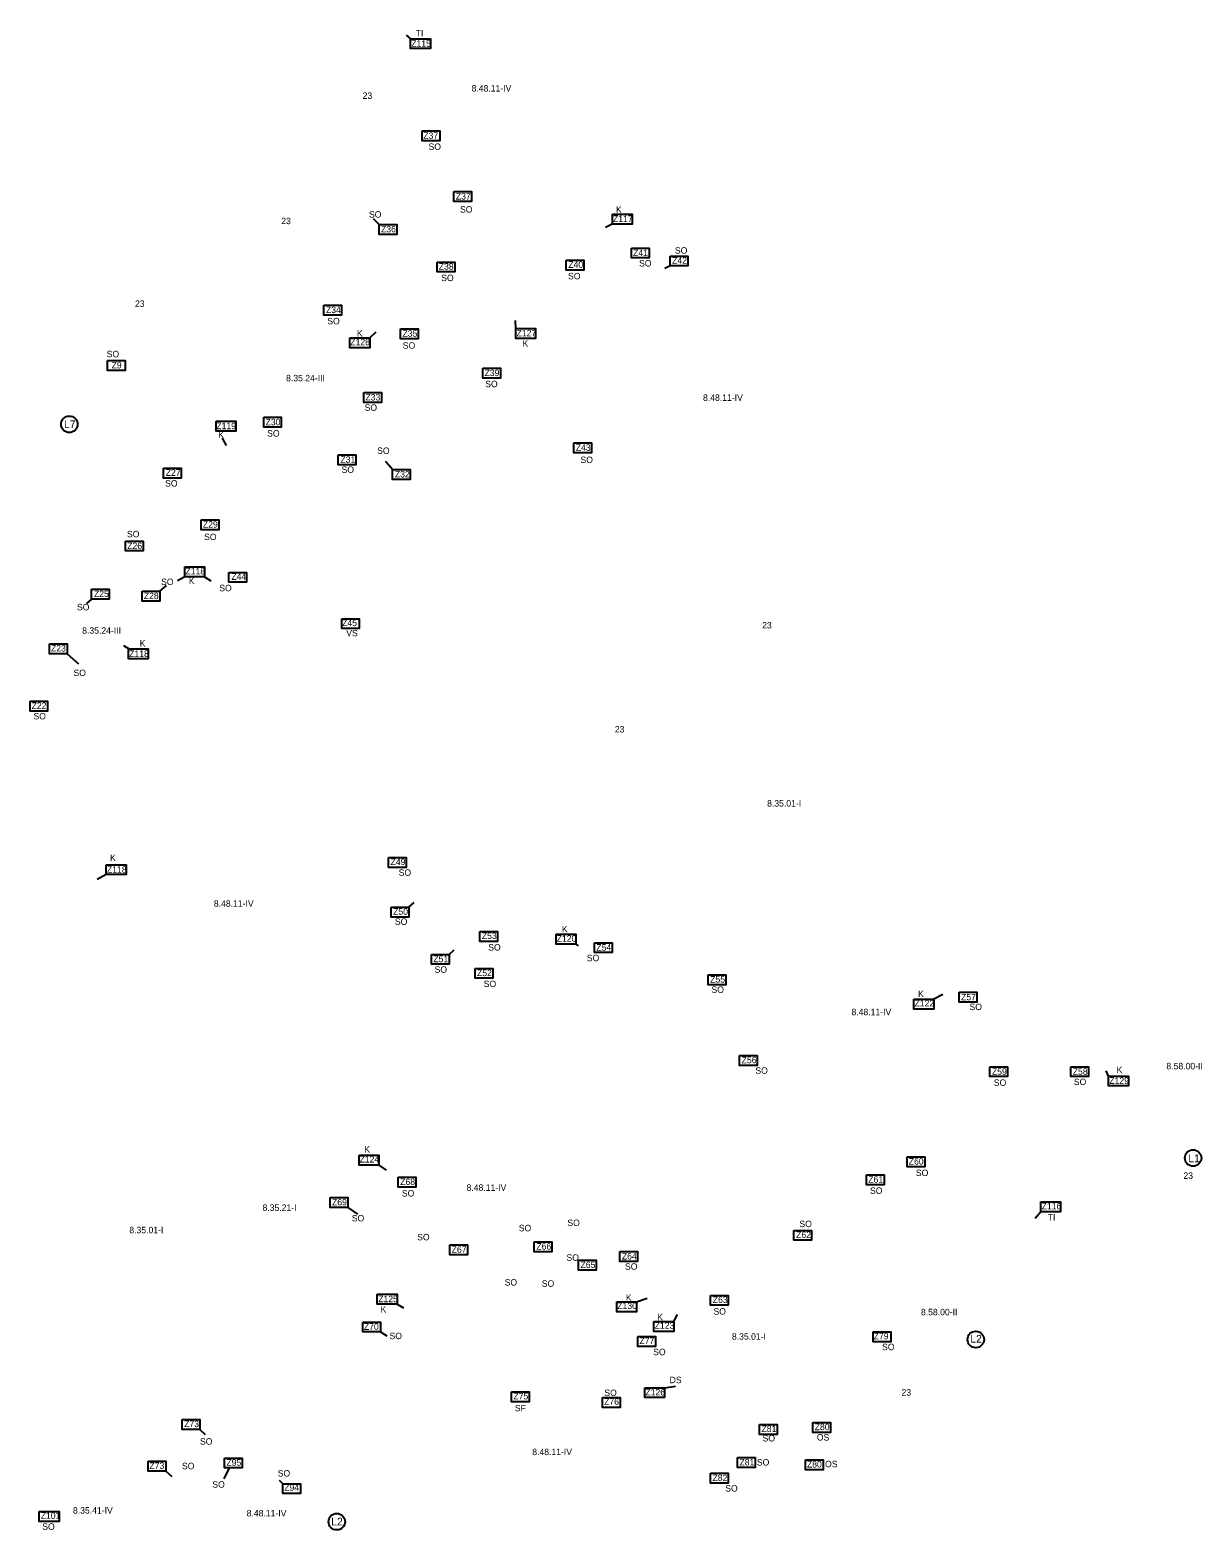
# Model space of a CAD drawing. Extents: x -450307 to -440553, y -1134449 to -1129789.
# Drawn here: x -442371 to -440553, y -1132115 to -1129789 of the extents above; entities that cross this region are included whole.
import ezdxf

# ---------------------------------------------------------------- set-up
doc = ezdxf.new("R2010")
doc.units = 0
for name, color, linetype in [('31_BUDOVY', 7, 'Continuous'), ('Vrstva 18', 7, 'Continuous'), ('Vrstva 28', 7, 'Continuous'), ('Vrstva 36', 7, 'Continuous')]:
    doc.layers.add(name, color=color, linetype=linetype)

msp = doc.modelspace()

# ---------------------------------------------------------------- linework, layer by layer
at = {"layer": '31_BUDOVY'}
msp.add_line((-441524.3, -1131206.4), (-441520.6, -1131209.2), dxfattribs=at)
at = {"layer": 'Vrstva 18'}
for p, q in [((-441780.2, -1129802.1), (-441786.8, -1129796.7)), ((-441829.1, -1130090.3), (-441838, -1130081.7)), ((-441467.9, -1130089.8), (-441478.3, -1130094.9)), ((-441378.1, -1130154.6), (-441386.2, -1130158.4)), ((-441617.6, -1130251.7), (-441617.8, -1130238.9)), ((-441834.5, -1130257.1), (-441844, -1130266.2)), ((-442066.2, -1130432.9), (-442072.4, -1130421.5)), ((-441808.5, -1130470.4), (-441819.7, -1130457.7)), ((-442169.8, -1130659.1), (-442159.4, -1130650.4)), ((-442131, -1130636.5), (-442142.2, -1130643.1)), ((-442100.3, -1130636.5), (-442090.5, -1130642.7)), ((-442275.3, -1130671.3), (-442283.1, -1130678.3)), ((-442217.8, -1130748.4), (-442225.3, -1130743.6)), ((-442313.2, -1130756), (-442295.7, -1130771.4)), ((-442252.6, -1131098.6), (-442266.5, -1131106.3)), ((-441783.2, -1131148.9), (-441775.1, -1131141.9)), ((-441721, -1131222.3), (-441712.8, -1131215.4)), ((-440955.2, -1131284.3), (-440969.1, -1131291.6)), ((-440697.9, -1131411.1), (-440701.8, -1131402.8)), ((-441829.7, -1131549.2), (-441818.5, -1131556.8)), ((-441878.2, -1131614.7), (-441862.9, -1131625)), ((-440803, -1131621.5), (-440811.7, -1131631.9)), ((-441801.4, -1131764.9), (-441791.5, -1131770.7)), ((-441430, -1131761), (-441413.5, -1131755.3)), ((-441372.3, -1131791.6), (-441366.8, -1131780.6)), ((-441827.4, -1131807.9), (-441817.5, -1131813.7)), ((-441386.6, -1131894.3), (-441369.7, -1131891.8)), ((-442107.7, -1131959.2), (-442099, -1131967)), ((-442160.4, -1132023.6), (-442151.1, -1132031.8)), ((-442061.8, -1132018.8), (-442070.5, -1132035.8)), ((-441978.8, -1132043.2), (-441984.2, -1132038.4))]:
    msp.add_line(p, q, dxfattribs=at)
for points in [[(-441780.6, -1129802.1), (-441749.8, -1129802.1), (-441749.8, -1129817.5), (-441780.6, -1129817.5)], [(-441762.9, -1129945.2), (-441735.5, -1129945.2), (-441735.5, -1129960.6), (-441762.9, -1129960.6)], [(-441713.5, -1130039.3), (-441686.2, -1130039.3), (-441686.2, -1130054.7), (-441713.5, -1130054.7)], [(-441467.6, -1130074.4), (-441436.8, -1130074.4), (-441436.8, -1130089.8), (-441467.6, -1130089.8)], [(-441829.1, -1130090.3), (-441801.8, -1130090.3), (-441801.8, -1130105.7), (-441829.1, -1130105.7)], [(-441539.4, -1130145.7), (-441512, -1130145.7), (-441512, -1130161.1), (-441539.4, -1130161.1)], [(-441438.1, -1130126.8), (-441410.7, -1130126.8), (-441410.7, -1130142.2), (-441438.1, -1130142.2)], [(-441378.1, -1130139.2), (-441350.7, -1130139.2), (-441350.7, -1130154.6), (-441378.1, -1130154.6)], [(-441739.6, -1130148.5), (-441712.2, -1130148.5), (-441712.2, -1130163.9), (-441739.6, -1130163.9)], [(-441915.1, -1130215.4), (-441887.7, -1130215.4), (-441887.7, -1130230.8), (-441915.1, -1130230.8)], [(-441796.3, -1130252.1), (-441768.9, -1130252.1), (-441768.9, -1130267.5), (-441796.3, -1130267.5)], [(-441617.6, -1130251.7), (-441586.8, -1130251.7), (-441586.8, -1130267.1), (-441617.6, -1130267.1)], [(-441874.8, -1130266.2), (-441844, -1130266.2), (-441844, -1130281.6), (-441874.8, -1130281.6)], [(-442250.7, -1130301.4), (-442223.3, -1130301.4), (-442223.3, -1130316.8), (-442250.7, -1130316.8)], [(-441668.4, -1130313.2), (-441641, -1130313.2), (-441641, -1130328.6), (-441668.4, -1130328.6)], [(-441853.1, -1130350.9), (-441825.7, -1130350.9), (-441825.7, -1130366.3), (-441853.1, -1130366.3)], [(-442082.4, -1130395.4), (-442051.6, -1130395.4), (-442051.6, -1130410.8), (-442082.4, -1130410.8)], [(-442008.5, -1130389.3), (-441981.2, -1130389.3), (-441981.2, -1130404.7), (-442008.5, -1130404.7)], [(-441893, -1130447.6), (-441865.6, -1130447.6), (-441865.6, -1130463), (-441893, -1130463)], [(-441527.5, -1130428.9), (-441500.2, -1130428.9), (-441500.2, -1130444.3), (-441527.5, -1130444.3)], [(-442163.9, -1130468.1), (-442136.5, -1130468.1), (-442136.5, -1130483.5), (-442163.9, -1130483.5)], [(-441808.5, -1130470.4), (-441781.1, -1130470.4), (-441781.1, -1130485.8), (-441808.5, -1130485.8)], [(-442105.4, -1130548.2), (-442078, -1130548.2), (-442078, -1130563.6), (-442105.4, -1130563.6)], [(-442222.8, -1130581.2), (-442195.5, -1130581.2), (-442195.5, -1130596.5), (-442222.8, -1130596.5)], [(-442130.8, -1130621.2), (-442100.1, -1130621.2), (-442100.1, -1130636.6), (-442130.8, -1130636.6)], [(-442062.5, -1130629.9), (-442035.1, -1130629.9), (-442035.1, -1130645.2), (-442062.5, -1130645.2)], [(-442275.3, -1130655.9), (-442247.9, -1130655.9), (-442247.9, -1130671.3), (-442275.3, -1130671.3)], [(-442197.1, -1130659.1), (-442169.8, -1130659.1), (-442169.8, -1130674.5), (-442197.1, -1130674.5)], [(-441887.5, -1130701.6), (-441860.2, -1130701.6), (-441860.2, -1130716.9), (-441887.5, -1130716.9)], [(-442340.6, -1130740.6), (-442313.2, -1130740.6), (-442313.2, -1130756), (-442340.6, -1130756)], [(-442218.1, -1130748.4), (-442187.4, -1130748.4), (-442187.4, -1130763.8), (-442218.1, -1130763.8)], [(-442370.9, -1130829.7), (-442343.6, -1130829.7), (-442343.6, -1130845.1), (-442370.9, -1130845.1)], [(-441815, -1131072), (-441787.6, -1131072), (-441787.6, -1131087.4), (-441815, -1131087.4)], [(-442252.6, -1131083.2), (-442221.9, -1131083.2), (-442221.9, -1131098.6), (-442252.6, -1131098.6)], [(-441810.6, -1131148.9), (-441783.2, -1131148.9), (-441783.2, -1131164.3), (-441810.6, -1131164.3)], [(-441673.2, -1131186.9), (-441645.8, -1131186.9), (-441645.8, -1131202.2), (-441673.2, -1131202.2)], [(-441555, -1131191), (-441524.3, -1131191), (-441524.3, -1131206.4), (-441555, -1131206.4)], [(-441495.6, -1131204.2), (-441468.2, -1131204.2), (-441468.2, -1131219.6), (-441495.6, -1131219.6)], [(-441748.4, -1131222.3), (-441721, -1131222.3), (-441721, -1131237.7), (-441748.4, -1131237.7)], [(-441680.5, -1131244), (-441653.2, -1131244), (-441653.2, -1131259.4), (-441680.5, -1131259.4)], [(-441319, -1131254), (-441291.6, -1131254), (-441291.6, -1131269.4), (-441319, -1131269.4)], [(-440929.5, -1131281), (-440902.2, -1131281), (-440902.2, -1131296.4), (-440929.5, -1131296.4)], [(-441000, -1131291.8), (-440969.2, -1131291.8), (-440969.2, -1131307.2), (-441000, -1131307.2)], [(-441270.2, -1131379), (-441242.8, -1131379), (-441242.8, -1131394.4), (-441270.2, -1131394.4)], [(-440882, -1131396.5), (-440854.6, -1131396.5), (-440854.6, -1131411.9), (-440882, -1131411.9)], [(-440756.3, -1131396.5), (-440728.9, -1131396.5), (-440728.9, -1131411.9), (-440756.3, -1131411.9)], [(-440697.9, -1131411.1), (-440667.2, -1131411.1), (-440667.2, -1131426.4), (-440697.9, -1131426.4)], [(-441860.5, -1131533.9), (-441829.7, -1131533.9), (-441829.7, -1131549.2), (-441860.5, -1131549.2)], [(-441010.2, -1131536.4), (-440982.9, -1131536.4), (-440982.9, -1131551.8), (-441010.2, -1131551.8)], [(-441073.4, -1131564.1), (-441046, -1131564.1), (-441046, -1131579.5), (-441073.4, -1131579.5)], [(-441799.8, -1131567.7), (-441772.4, -1131567.7), (-441772.4, -1131583.1), (-441799.8, -1131583.1)], [(-441905.5, -1131599.3), (-441878.2, -1131599.3), (-441878.2, -1131614.7), (-441905.5, -1131614.7)], [(-440803, -1131606.1), (-440772.3, -1131606.1), (-440772.3, -1131621.5), (-440803, -1131621.5)], [(-441186, -1131650.3), (-441158.6, -1131650.3), (-441158.6, -1131665.7), (-441186, -1131665.7)], [(-441719.9, -1131672.7), (-441692.5, -1131672.7), (-441692.5, -1131688.1), (-441719.9, -1131688.1)], [(-441588.7, -1131668), (-441561.3, -1131668), (-441561.3, -1131683.4), (-441588.7, -1131683.4)], [(-441520.2, -1131696.6), (-441492.8, -1131696.6), (-441492.8, -1131712), (-441520.2, -1131712)], [(-441455.9, -1131683.3), (-441428.5, -1131683.3), (-441428.5, -1131698.7), (-441455.9, -1131698.7)], [(-441832.2, -1131749.5), (-441801.4, -1131749.5), (-441801.4, -1131764.9), (-441832.2, -1131764.9)], [(-441315.3, -1131751.1), (-441287.9, -1131751.1), (-441287.9, -1131766.5), (-441315.3, -1131766.5)], [(-441460.7, -1131761), (-441430, -1131761), (-441430, -1131776.4), (-441460.7, -1131776.4)], [(-441854.8, -1131792.5), (-441827.4, -1131792.5), (-441827.4, -1131807.9), (-441854.8, -1131807.9)], [(-441403.1, -1131791.6), (-441372.3, -1131791.6), (-441372.3, -1131807), (-441403.1, -1131807)], [(-441428.1, -1131814.9), (-441400.7, -1131814.9), (-441400.7, -1131830.2), (-441428.1, -1131830.2)], [(-441063.1, -1131807.7), (-441035.7, -1131807.7), (-441035.7, -1131823), (-441063.1, -1131823)], [(-441624.2, -1131900.8), (-441596.8, -1131900.8), (-441596.8, -1131916.2), (-441624.2, -1131916.2)], [(-441482.9, -1131909.4), (-441455.5, -1131909.4), (-441455.5, -1131924.8), (-441482.9, -1131924.8)], [(-441417.4, -1131894.3), (-441386.6, -1131894.3), (-441386.6, -1131909.7), (-441417.4, -1131909.7)], [(-442135.1, -1131943.8), (-442107.7, -1131943.8), (-442107.7, -1131959.2), (-442135.1, -1131959.2)], [(-441239.2, -1131951.6), (-441211.8, -1131951.6), (-441211.8, -1131967), (-441239.2, -1131967)], [(-441156.9, -1131948.4), (-441129.5, -1131948.4), (-441129.5, -1131963.8), (-441156.9, -1131963.8)], [(-442069.1, -1132003.4), (-442041.7, -1132003.4), (-442041.7, -1132018.8), (-442069.1, -1132018.8)], [(-441273.5, -1132002.7), (-441246.1, -1132002.7), (-441246.1, -1132018.1), (-441273.5, -1132018.1)], [(-441168.2, -1132006.3), (-441140.8, -1132006.3), (-441140.8, -1132021.7), (-441168.2, -1132021.7)], [(-442187.8, -1132008.2), (-442160.4, -1132008.2), (-442160.4, -1132023.6), (-442187.8, -1132023.6)], [(-441315.4, -1132026.8), (-441288, -1132026.8), (-441288, -1132042.2), (-441315.4, -1132042.2)], [(-441978.8, -1132043.2), (-441951.5, -1132043.2), (-441951.5, -1132058.6), (-441978.8, -1132058.6)], [(-442356.5, -1132086.3), (-442325.7, -1132086.3), (-442325.7, -1132101.7), (-442356.5, -1132101.7)]]:
    msp.add_lwpolyline(points, close=True, dxfattribs=at)
at = {"layer": 'Vrstva 36'}
for centre in [(-442310, -1130400.1), (-440566.9, -1131538.1), (-440903.9, -1131819.5), (-441895.1, -1132102.2)]:
    msp.add_circle(centre, 12.8, dxfattribs=at)

# ---------------------------------------------------------------- texts
at = {"layer": 'Vrstva 18'}
for s, p in [('TI', (-441772.6, -1129798.6)), ('Z115', (-441779.6, -1129814.6)), ('Z37', (-441761, -1129957.5)), ('SO', (-441752.8, -1129974.6)), ('Z37', (-441710.4, -1130051.5)), ('SO', (-441845.2, -1130079.6)), ('SO', (-441703.9, -1130071.8)), ('Z117', (-441466.6, -1130086.3)), ('K', (-441462, -1130072)), ('Z36', (-441826.5, -1130102.5)), ('Z41', (-441435.5, -1130139.1)), ('SO', (-441426.3, -1130155.4)), ('Z42', (-441374.9, -1130151)), ('SO', (-441370.6, -1130135.5)), ('Z38', (-441736.9, -1130160.4)), ('SO', (-441733.1, -1130178.1)), ('SO', (-441536.4, -1130175.3)), ('Z40', (-441536, -1130157.5)), ('Z34', (-441911.9, -1130227.7)), ('SO', (-441909.8, -1130245.1)), ('K', (-441863.9, -1130264.1)), ('Z35', (-441793.1, -1130264.3)), ('Z127', (-441616.2, -1130263.7)), ('SO', (-442252, -1130296.2)), ('Z128', (-441874.1, -1130277.5)), ('SO', (-441792.8, -1130282.9)), ('K', (-441607, -1130279.8)), ('Z9', (-442244.4, -1130313.5)), ('Z39', (-441665.9, -1130325.4)), ('SO', (-441664.8, -1130342.6)), ('Z33', (-441850.7, -1130363.2)), ('SO', (-441851.9, -1130379.2)), ('Z119', (-442081.9, -1130407.7)), ('Z30', (-442005.5, -1130401.6)), ('K', (-442079, -1130421.6)), ('SO', (-442003.1, -1130419.2)), ('SO', (-441832.5, -1130446.1)), ('Z43', (-441524.3, -1130441.2)), ('Z27', (-442160.4, -1130480.1)), ('Z31', (-441889.4, -1130459.9)), ('SO', (-441887.7, -1130475.5)), ('SO', (-441517.1, -1130460.2)), ('SO', (-442161.4, -1130496.7)), ('Z32', (-441805, -1130482.6)), ('SO', (-442220.5, -1130575.4)), ('Z29', (-442102.7, -1130560.4)), ('Z26', (-442220.1, -1130593.6)), ('SO', (-442100.9, -1130579.7)), ('Z118', (-442129.8, -1130632.9)), ('Z44', (-442058.6, -1130641.4)), ('Z25', (-442271.7, -1130668)), ('SO', (-442167.6, -1130649.4)), ('K', (-442124.6, -1130648)), ('SO', (-442077.3, -1130659.1)), ('SO', (-442298.1, -1130688.6)), ('Z28', (-442194.4, -1130671.3)), ('Z45', (-441886.8, -1130713.2)), ('VS', (-441880.4, -1130729)), ('Z23', (-442338.4, -1130752.5)), ('Z118', (-442217.1, -1130760.9)), ('K', (-442200.8, -1130744.9)), ('SO', (-442303.5, -1130790.6)), ('Z22', (-442368.4, -1130841.6)), ('SO', (-442365.6, -1130857.8)), ('K', (-442246.8, -1131077.4)), ('Z49', (-441811.7, -1131083.8)), ('Z118', (-442251.6, -1131095.6)), ('SO', (-441799.1, -1131100.4)), ('Z50', (-441807.7, -1131160.9)), ('SO', (-441804.9, -1131176.4)), ('Z53', (-441670.1, -1131198.5)), ('Z120', (-441554, -1131202.7)), ('K', (-441545.8, -1131188.1)), ('SO', (-441660.2, -1131216.3)), ('Z54', (-441492.5, -1131216.4)), ('Z51', (-441745.4, -1131234.4)), ('SO', (-441507.3, -1131232.8)), ('SO', (-441743.4, -1131250.8)), ('Z52', (-441677.6, -1131256)), ('SO', (-441667.2, -1131273)), ('Z55', (-441315.9, -1131266)), ('SO', (-441313.9, -1131282)), ('K', (-440993.5, -1131288.5)), ('Z57', (-440926.8, -1131293.5)), ('Z122', (-440999, -1131303.1)), ('SO', (-440913.7, -1131308.7)), ('Z56', (-441267.1, -1131391.1)), ('SO', (-441245.8, -1131407.4)), ('Z59', (-440878.9, -1131409)), ('Z58', (-440753.5, -1131409)), ('K', (-440685.5, -1131406.5)), ('SO', (-440876, -1131426.2)), ('SO', (-440751.9, -1131425)), ('Z129', (-440696.9, -1131423.1)), ('Z124', (-441859.8, -1131545.1)), ('K', (-441852.5, -1131529.7)), ('Z60', (-441007.9, -1131548.3)), ('SO', (-440996.9, -1131566.1)), ('Z68', (-441796.7, -1131580)), ('SO', (-441794.2, -1131597.8)), ('Z61', (-441070.7, -1131576.3)), ('SO', (-441068, -1131593.7)), ('Z69', (-441902.5, -1131611.6)), ('Z116', (-440801.8, -1131617.8)), ('SO', (-441871.8, -1131636.4)), ('SO', (-441537.4, -1131643.6)), ('SO', (-441177.5, -1131645.3)), ('TI', (-440792.4, -1131635.1)), ('SO', (-441770.4, -1131665.8)), ('SO', (-441612.8, -1131651.7)), ('Z62', (-441182.6, -1131662.1)), ('Z67', (-441716.9, -1131685)), ('Z66', (-441585.5, -1131680.1)), ('SO', (-441538.8, -1131697.5)), ('Z65', (-441517, -1131708.6)), ('Z64', (-441452.9, -1131695.5)), ('SO', (-441448.1, -1131711.4)), ('SO', (-441634.7, -1131735.9)), ('SO', (-441577.1, -1131737.8)), ('Z125', (-441830.8, -1131761.7)), ('K', (-441446.7, -1131759.5)), ('K', (-441827.2, -1131777.9)), ('Z130', (-441460.1, -1131772.3)), ('Z63', (-441311.9, -1131762.9)), ('SO', (-441310.8, -1131781)), ('Z70', (-441853.1, -1131804.6)), ('Z123', (-441402, -1131802.9)), ('K', (-441398.1, -1131789.7)), ('SO', (-441813.3, -1131819)), ('Z77', (-441425.7, -1131826.8)), ('Z79', (-441062.3, -1131819.3)), ('SO', (-441404.3, -1131843.9)), ('SO', (-441049.3, -1131836.1)), ('DS', (-441378.8, -1131887.3)), ('Z75', (-441621.1, -1131912.5)), ('Z76', (-441480.4, -1131920.8)), ('SO', (-441480.1, -1131907.2)), ('Z126', (-441416.4, -1131906.3)), ('SF', (-441618.9, -1131931)), ('Z73', (-442131.8, -1131955.5)), ('Z81', (-441236.3, -1131963.1)), ('Z80', (-441153.8, -1131960.2)), ('SO', (-442107.3, -1131982.6)), ('SO', (-441234.7, -1131977.7)), ('OS', (-441150.5, -1131976.3)), ('Z95', (-442066.3, -1132015.4)), ('Z81', (-441270.5, -1132014.9)), ('SO', (-441243.5, -1132015)), ('OS', (-441137.7, -1132017.7)), ('Z73', (-442185.7, -1132020.3)), ('SO', (-442135.2, -1132020.8)), ('SO', (-441986.7, -1132032.1)), ('Z82', (-441312.3, -1132039.2)), ('Z80', (-441165.9, -1132018.1)), ('SO', (-442088.1, -1132049.4)), ('Z94', (-441976.6, -1132054.2)), ('SO', (-441292.5, -1132055.4)), ('Z101', (-442354.3, -1132097.7)), ('SO', (-442351.9, -1132114.7))]:
    msp.add_text(s, height=10, dxfattribs=at).set_placement(p)
at = {"layer": 'Vrstva 28'}
for s, p in [('23', (-441855, -1129895.4)), ('8.48.11-IV', (-441686, -1129884)), ('23', (-441981.2, -1130089.7)), ('23', (-442208.1, -1130218.1)), ('8.35.24-III', (-441973.7, -1130333.5)), ('8.48.11-IV', (-441327, -1130363.8)), ('8.35.24-III', (-442290, -1130724.9)), ('23', (-441235.3, -1130716.7)), ('23', (-441463.8, -1130878.1)), ('8.35.01-I', (-441227.6, -1130993)), ('8.48.11-IV', (-442085.7, -1131148.3)), ('8.48.11-IV', (-441096.8, -1131316.6)), ('8.58.00-II', (-440608.3, -1131400.5)), ('23', (-440581.9, -1131570.4)), ('8.48.11-IV', (-441693.8, -1131589)), ('8.35.21-I', (-442010.3, -1131620.1)), ('8.35.01-I', (-442216.9, -1131654.8)), ('8.58.00-II', (-440989, -1131782)), ('8.35.01-I', (-441282.2, -1131819.9)), ('23', (-441019.1, -1131906.5)), ('8.48.11-IV', (-441591.9, -1131998.9)), ('8.35.41-IV', (-442304.3, -1132089.6)), ('8.48.11-IV', (-442034.9, -1132093.9))]:
    msp.add_text(s, height=10, dxfattribs=at).set_placement(p)
at = {"layer": 'Vrstva 36'}
for s, p in [('L7', (-442318.2, -1130406.1)), ('L1', (-440574.3, -1131544.6)), ('L2', (-440912.4, -1131824.4)), ('L2', (-441903.6, -1132107.9))]:
    msp.add_text(s, height=12, dxfattribs=at).set_placement(p)

doc.saveas('drawing.dxf')
